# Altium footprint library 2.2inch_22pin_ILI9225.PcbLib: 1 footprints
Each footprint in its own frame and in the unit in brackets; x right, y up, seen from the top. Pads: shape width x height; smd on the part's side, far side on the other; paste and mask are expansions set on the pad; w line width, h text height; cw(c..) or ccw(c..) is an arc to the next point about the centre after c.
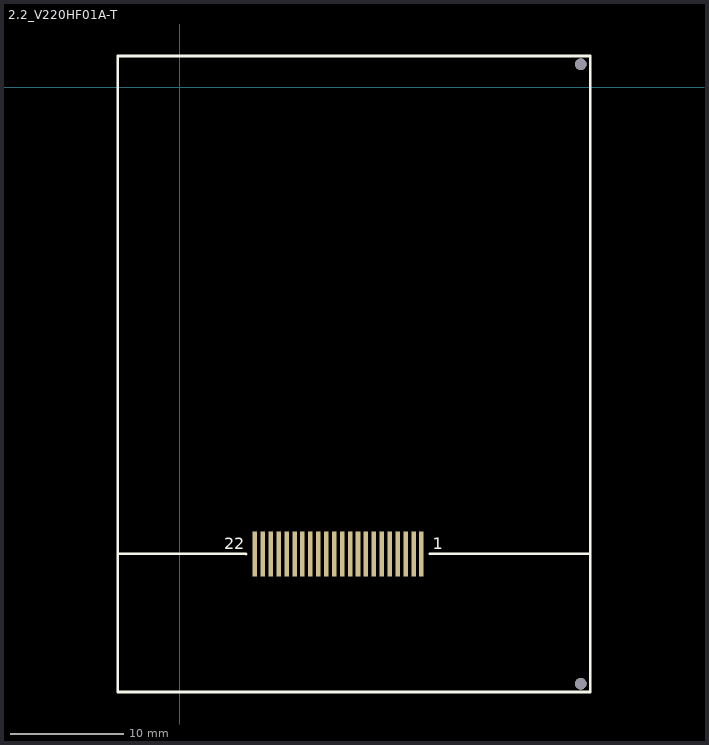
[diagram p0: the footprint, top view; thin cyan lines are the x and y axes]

## 2.2_V220HF01A-T [mm] "LCD"
pads (22):
  rect 0.4x4 smd: 1(21.342,-41.166) 2(20.642,-41.166) 3(19.942,-41.166) 4(19.242,-41.166) 5(18.542,-41.166) 6(17.842,-41.166) 7(17.142,-41.166) 8(16.442,-41.166) 9(15.742,-41.166) 10(15.042,-41.166) 11(14.342,-41.166) 12(13.642,-41.166) 13(12.942,-41.166) 15(11.542,-41.166) 16(10.842,-41.166) 17(10.142,-41.166) 18(9.442,-41.166) 19(8.742,-41.166) 20(8.042,-41.166) 21(7.342,-41.166) 22(6.642,-41.166) 149(12.242,-41.166)
via 35.389,-52.616 diameter 1 hole 1
via 35.389,2.044 diameter 1 hole 1
Top Overlay:
  lines w0.254: -5.461,-53.366 36.239,-53.366 ; -5.461,-53.355 -5.461,2.794 36.239,2.794 36.239,-53.355 ; -5.461,-41.148 5.842,-41.166 ; 22.098,-41.148 36.239,-41.148
  text "22" at 3.937,-40.767 h1.02
  text "1" at 22.352,-40.767 h1.02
